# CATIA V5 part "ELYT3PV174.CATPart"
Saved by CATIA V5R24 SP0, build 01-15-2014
Part number: ELYT3PV174
Material "ZAMA": density 6700 kg/m3
Material "ZAMA": density 6700 kg/m3
Bounding box of the stored display mesh (mm): x -59 to 27.5, y 0 to 1740, z 0 to 1500
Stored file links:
  \\mnsrv021stg\Common\AREA TECNICA\Documenti\3D sito\Componenti risolti\ELYT3PV174.CATPart
  Z:\commesse\Novellini\Serie Zephiros\BH01S66\ID_18668_00.CATPart
  Z:\commesse\Novellini\Prove\Tabelladiprogetto1.txt
  Z:\commesse\Novellini\Prove\Tabelladiprogetto2.xls
  C:\Users\n.rebecchi\Desktop\Scambio\ID_35222_00.xls
  Z:\3D sito\BH02A.xlsx
  \\MNSRV021STG\Common\AREA TECNICA\Documenti\3D sito\BOX\ZEPHIROS\BH02A\BH02A.xls
  Z:\3D sito\ZEPHIROS\BH022P\BH022P.xls
  C:\Docisland\DocIsland\catia_workdir\diclient\N.REBECCHI\ID_21111_03.CATPart
  C:\Docisland\DocIsland\catia_workdir\diclient\N.REBECCHI\ID_29051_00.CATPart
  U:\AREA TECNICA\Documenti\3D sito\BOX\ZEPHYROS\ZEPHYR3P\BH013P.xls
  \\mnsrv021stg\Common\AREA TECNICA\Documenti\3D sito\BOX\ELYT\ZEPHYR3P\ELYT3PV.xls
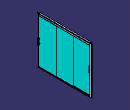
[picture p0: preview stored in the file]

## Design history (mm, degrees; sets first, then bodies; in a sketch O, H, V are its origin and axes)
Parameters
  `Larghezza anta` = 561 mm
  `MISURA NOMINALE` = 1740 mm
  PartNumber = "ELYT3PV174"
  `Lunghezza binario` = 1646 mm
Pad1: profile Sketch3.L13, length 1441, opposite side length -21
Solid1: solid without history
Solid2: solid without history
Pad2: profile Sketch3.L6, length 1441, opposite side length -21
Sketch1 on xy-plane, origin (0, 0, 0), H (1, 0, 0), V (0, 1, 0)
  axis line L1 (84.1025, 870) -> (-125.0839, 870)
  point P3 (-18.5, 0)
  point P4 (-18.5, 52.3)
  point P5 (0, 50.8)
  point P6 (-1.5, 52.3)
  point P8 (0, 1.5)
  point P9 (-1.5, 0)
  line L2 (0, 50.8) -> (0, 1.5)
  line L3 (-1.5, 0) -> (-32.75, 0)
  line L4 (-18.5, 1.5) -> (-18.5, 52.3)
  line L5 (-18.5, 52.3) -> (-1.5, 52.3)
  arc A1 centre (-1.5, 50.8) radius 1.5 from (0, 50.8) to (-1.5, 52.3) ccw
  arc A2 centre (-1.5, 1.5) radius 1.5 from (0, 1.5) to (-1.5, 0) cw
  line L6 (-18.5, 1.5) -> (-32.75, 1.5)
  point P11 (-32.75, 1.5)
  arc A3 centre (-32.75, 0.75) radius 0.75 from (-32.75, 1.5) to (-32.75, 0) ccw
  point P13 (-32.75, 0)
  point P14 (-18.5, 1.5)
  point P15 (-3, 1307.7)
  construction line L7 through (-1555.4, 0) direction (-1, 0)
  construction line L8 through (-1255.4, 0) direction (0, 1)
  point P16 (-18.5, 1740)
  point P17 (-18.5, 1687.7)
  point P18 (0, 1689.2)
  point P19 (-1.5, 1687.7)
  point P21 (0, 1738.5)
  point P22 (-1.5, 1740)
  point P24 (-32.75, 1738.5)
  point P26 (-32.75, 1740)
  point P27 (-18.5, 1738.5)
  line L9 (0, 1689.2) -> (0, 1738.5)
  line L10 (-1.5, 1740) -> (-32.75, 1740)
  line L11 (-18.5, 1738.5) -> (-18.5, 1689.1)
  line L12 (-52, 1687.7) -> (-1.5, 1687.7)
  arc A4 centre (-1.5, 1689.2) radius 1.5 from (0, 1689.2) to (-1.5, 1687.7) cw
  arc A5 centre (-1.5, 1738.5) radius 1.5 from (0, 1738.5) to (-1.5, 1740) ccw
  line L13 (-18.5, 1738.5) -> (-32.75, 1738.5)
  arc A6 centre (-32.75, 1739.25) radius 0.75 from (-32.75, 1738.5) to (-32.75, 1740) cw
  line L14 (-52, 1687.7) -> (-52, 1698.2)
  line L15 (-52, 1698.2) -> (-37, 1698.2)
  line L16 (-37, 1698.2) -> (-37, 1689.1)
  line L17 (-37, 1689.1) -> (-18.5, 1689.1)
  length L5 = 17
  radius A1 = 1.5
  distance L6 L3 = 1.5
  distance L4 A3 = 15
  distance L5 L3 = 52.3
  distance L2 L4 = 18.5
  radius A2 = 1.5
  distance L10 L3 = 1740 {= `MISURA NOMINALE`}
  distance L9 L14 = 52
  length L15 = 15
  distance L12 L17 = 1.4
  distance L15 L12 = 10.5
  tangency: A1 L2, A3 L3, A3 L6, L2 A2, A2 L3
  coincidence: P3 L3, P17 L11, P17 L12, L2 V, L3 L7, L3 H
  symmetry: P3 P16 L1, P4 P17 L1, P5 P18 L1, P6 P19 L1, P8 P21 L1, P9 P22 L1, P11 P24 L1, P13 P26 L1, P14 P27 L1, L2 L9 L1, L3 L10 L1, L4 L11 L1, L5 L12 L1, A1 A4 L1, A2 A5 L1, L6 L13 L1, A3 A6 L1
  vertical: L16 V
Pad3: profile Sketch1, direction (0, 0, 1), length 1500
Body1 "Telaio" (main body)
  Sketch2 on face of Pad3 from Sketch1.L5, origin (0, 52.3, 0), H (-1, 0, 0), V (0, 0, -1)
    point P1 (-1, -1500)
    line L1 (5.7859, -1500) -> (52.2221, -1500)
    line L2 (59, -1485.3692) -> (59, -1437.2118)
    construction line L3 (247.7599, -1440) -> (58, -1440)
    line L4 (-1, -1436.5) -> (-1, -1485.3692)
    point P2 (59, -1500)
    point P3 (59, -1440)
    construction line L5 (57.5, -1498) -> (57.5, -1486.5)
    construction line L6 (190.2599, -1498) -> (4.1139, -1498)
    point P5 (57.5, -1498)
    line L7 (57.7882, -1436) -> (-0.5, -1436)
    construction line L8 (8.597, -1485.5) -> (18.6226, -1485.5)
    construction line L9 (1.7786, -1486.5) -> (4.2562, -1486.5)
    construction line L10 (57.5, -1485.2) -> (57.5, -1440.5)
    construction line L11 (1, -1485) -> (1, -1464.277)
    point P6 (57.5, -1486.5)
    point P7 (1, -1485.5)
    construction line L12 (36.5779, -1495.9874) -> (36.5305, -1488.4874)
    construction line L13 (37.7781, -1496.0126) -> (37.7307, -1488.5126)
    construction line L14 (39.7307, -1486.5) -> (53.9552, -1486.5)
    construction line L15 (39.778, -1498) -> (50.7716, -1498)
    construction line L16 (18.9226, -1496) -> (18.9226, -1488.5)
    construction line L17 (20.1226, -1496) -> (20.1226, -1486.8)
    construction line L18 (20.4226, -1486.5) -> (34.5306, -1486.5)
    construction line L19 (22.1226, -1498) -> (34.5779, -1498)
    construction line L20 (18.9226, -1485.2) -> (18.9226, -1464.6071)
    construction line L21 (20.1226, -1485.2) -> (20.1226, -1466.4658)
    construction line L22 (36.5098, -1485.1981) -> (36.3815, -1464.8702)
    construction line L23 (37.7098, -1485.2019) -> (37.5963, -1467.2104)
    construction line L24 (20.4226, -1485.5) -> (222.4284, -1485.5)
    construction line L25 (38.0098, -1485.5) -> (57.2, -1485.5)
    construction line L26 (0.5, -1461.4168) -> (0.5, -1436.5)
    construction line L27 (46.4222, -1915.0185) -> (46.406, -1912.4534)
    construction line L28 (46.4222, -1915.0185) -> (47.9222, -1915.0091)
    construction arc A1 centre (8.7492, -1464.5115) radius 0.25 from (8.9992, -1464.5065) to (8.701, -1464.7568) cw
    construction arc A2 centre (5.7, -1465.25) radius 2.75 from (3.3803, -1463.773) to (8.3995, -1464.7254) cw
    point P12 (5.7, -1465.25)
    construction line L29 (1.4989, -1463.777) -> (3.3803, -1463.773)
    construction arc A3 centre (4.9238, -1464.5873) radius 4.0762 from (1.9856, -1461.762) to (9, -1464.5873) cw
    point P14 (8.9992, -1464.5065)
    construction arc A4 centre (8.7975, -1464.2662) radius 0.5 from (8.701, -1464.7568) to (8.321, -1464.4175) cw
    point P16 (8.321, -1464.4175)
    point P18 (23.1853, -1465.9683)
    point P19 (21.993, -1463.4903)
    point P20 (25.9312, -1465.8199)
    construction arc A5 centre (23.1853, -1465.9683) radius 2.75 from (21.993, -1463.4903) to (25.9123, -1465.6134) cw
    construction arc A6 centre (26.4305, -1465.7929) radius 0.5 from (25.9918, -1465.553) to (25.9312, -1465.8199) cw
    construction arc A7 centre (26.2112, -1465.6729) radius 0.25 from (26.45, -1465.7469) to (25.9918, -1465.553) cw
    construction arc A8 centre (23.4246, -1466.4658) radius 3.302 from (20.1226, -1466.4658) to (21.993, -1463.4903) cw
    point P24 (21.9929, -1463.4903)
    point P27 (40.6705, -1466.6867)
    construction arc A9 centre (43.6396, -1465.9948) radius 0.25 from (43.8765, -1466.0746) to (43.4818, -1466.1887) cw
    point P30 (43.3164, -1465.9372)
    construction arc A10 centre (43.7975, -1465.8009) radius 0.5 from (43.4818, -1466.1887) to (43.3164, -1465.9372) cw
    construction arc A11 centre (40.6705, -1466.6867) radius 2.75 from (39.5358, -1464.1817) to (43.3323, -1465.9959) cw
    construction arc A12 centre (40.8983, -1467.1895) radius 3.302 from (37.5963, -1467.2104) to (39.5358, -1464.1817) cw
    point P35 (211.7599, -1486.5)
    point P36 (12.6022, -1750.9456)
    point P37 (12.601, -1748.9456)
    point P38 (7.2208, -1496)
    point P39 (11.602, -1750.6462)
    point P40 (7.6073, -1494.5506)
    point P41 (7.6108, -1497.4484)
    point P42 (6.7699, -1497.6909)
    point P43 (5.9208, -1495.2516)
    point P44 (7.9723, -1497.2981)
    point P45 (5.9208, -1495.2516)
    point P46 (6.1845, -1494.2101)
    point P47 (7.9723, -1497.2981)
    point P48 (6.1845, -1494.2101)
    point P49 (6.7699, -1497.6909)
    point P50 (7.6073, -1494.5506)
    point P51 (7.6757, -1497.6898)
    point P52 (8.7353, -1495.1232)
    point P53 (5.9226, -1496.7516)
    point P54 (8.7353, -1495.1232)
    point P55 (5.9226, -1496.7516)
    point P56 (7.9692, -1494.7001)
    point P57 (7.9692, -1494.7001)
    point P58 (7.6108, -1497.4484)
    point P59 (7.6757, -1497.6898)
    construction arc A13 centre (7.2208, -1496) radius 1.5 from (7.6073, -1494.5506) to (7.6108, -1497.4484) ccw
    construction arc A14 centre (7.2208, -1496) radius 1.75 from (5.7042, -1495.1268) to (6.7699, -1497.6909) ccw
    construction line L30 (5.7042, -1495.1268) -> (5.9208, -1495.2516)
    construction arc A15 centre (7.2208, -1496) radius 1.5 from (7.9723, -1497.2981) to (5.9208, -1495.2516) ccw
    construction line L31 (6.1845, -1494.2101) -> (7.9723, -1497.2981)
    construction arc A16 centre (5.5354, -1494.5859) radius 0.75 from (6.1845, -1494.2101) to (5.5317, -1495.3359) ccw
    construction line L32 (6.7699, -1497.6909) -> (7.6073, -1494.5506)
    construction arc A17 centre (7.2208, -1496) radius 1.75 from (7.6757, -1497.6898) to (8.7353, -1495.1232) ccw
    construction line L33 (5.9226, -1496.7516) -> (8.7353, -1495.1232)
    construction arc A18 centre (7.2208, -1496) radius 1.5 from (5.9226, -1496.7516) to (7.9692, -1494.7001) ccw
    construction line L34 (7.9692, -1494.7001) -> (8.2527, -1494.2076)
    construction arc A19 centre (8.9027, -1494.5818) radius 0.75 from (9.4761, -1494.0984) to (8.2527, -1494.2076) ccw
    construction arc A20 centre (7.2208, -1496) radius 2.95 from (4.9609, -1494.1038) to (5.5608, -1493.5613) ccw
    construction line L35 (7.6108, -1497.4484) -> (7.6757, -1497.6898)
    point P60 (196.5645, -1917.6542)
    point P61 (11.6031, -1752.3962)
    point P62 (167.077, -1877.6984)
    construction line L36 (7.2208, -1496) -> (7.769, -1950.7895)
    point P63 (7.769, -1950.7895)
    construction line L37 (7.2208, -1496) -> (-0.9278, -1496)
    point P65 (4.9609, -1494.1038)
    point P67 (7.2232, -1498)
    construction line L38 (10.3276, -1498) -> (16.9226, -1498)
    construction arc A21 centre (4.1139, -1497.5) radius 0.5 from (4.5642, -1497.2826) to (4.1139, -1498) cw
    point P68 (4.5642, -1497.2826)
    construction arc A22 centre (7.2208, -1496) radius 2.95 from (9.4761, -1494.0984) to (9.8774, -1497.2826) cw
    construction arc A23 centre (10.3276, -1497.5) radius 0.5 from (9.8774, -1497.2826) to (10.3276, -1498) ccw
    point P74 (195.3181, -1910.0413)
    point P75 (197.3181, -1910.0413)
    point P77 (195.6181, -1911.0413)
    point P78 (193.8681, -1911.0413)
    point P79 (194.0428, -1910.0413)
    construction line L39 (198.7599, -1909.6171) -> (198.7599, -1904.8275)
    point P81 (196.7599, -1907.6171)
    construction line L40 (7.5212, -1762.7716) -> (7.5105, -1745.0224)
    point P85 (2.4259, -1750.9517)
    point P86 (2.4247, -1748.9517)
    point P88 (3.4257, -1750.6511)
    point P89 (3.4268, -1752.4011)
    point P90 (-151.896, -1877.8906)
    point P91 (7.5, -1950.7897)
    construction line L41 (7.5, -1935.9877) -> (7.5, -1950.7897)
    point P92 (7.5, -1497.9998)
    point P93 (2.4259, -1750.9517)
    point P94 (2.4247, -1748.9517)
    point P95 (7.5, -1487)
    point P96 (3.4257, -1750.6511)
    point P97 (7.8882, -1488.4489)
    point P98 (7.1118, -1488.4489)
    point P99 (7.9529, -1488.6904)
    point P100 (8.799, -1486.25)
    point P101 (8.25, -1485.701)
    point P102 (8.799, -1486.25)
    point P103 (8.5378, -1485.2025)
    point P104 (8.25, -1485.701)
    point P105 (8.5378, -1485.2025)
    point P106 (7.9529, -1488.6904)
    point P107 (7.8882, -1488.4489)
    point P108 (7.0471, -1488.6904)
    point P109 (5.9845, -1486.125)
    point P110 (6.201, -1486.25)
    point P111 (5.9845, -1486.125)
    point P112 (6.201, -1486.25)
    point P113 (6.75, -1485.701)
    point P114 (6.75, -1485.701)
    point P115 (7.1118, -1488.4489)
    point P116 (7.0471, -1488.6904)
    point P117 (3.4268, -1752.4011)
    point P118 (-151.896, -1877.8906)
    point P119 (7.5, -1950.7897)
    construction line L42 (7.5, -1487) -> (7.5, -1950.7897)
    point P120 (6.4659, -1485.2089)
    point P121 (7.5, -1497.9998)
    construction arc A24 centre (7.5, -1487) radius 1.5 from (7.8882, -1488.4489) to (7.1118, -1488.4489) cw
    construction arc A25 centre (7.5, -1487) radius 1.75 from (9.0155, -1486.125) to (7.9529, -1488.6904) cw
    construction line L43 (9.0155, -1486.125) -> (8.799, -1486.25)
    construction arc A26 centre (7.5, -1487) radius 1.5 from (8.25, -1485.701) to (8.799, -1486.25) cw
    construction line L44 (8.2506, -1485.7) -> (8.25, -1485.701)
    construction arc A27 centre (9.1873, -1485.5775) radius 0.75 from (8.5378, -1485.2025) to (9.6782, -1485.0105) cw
    construction line L45 (7.9529, -1488.6904) -> (7.8882, -1488.4489)
    construction arc A28 centre (7.5, -1487) radius 1.75 from (7.0471, -1488.6904) to (5.9845, -1486.125) cw
    construction line L46 (6.201, -1486.25) -> (5.9845, -1486.125)
    construction arc A29 centre (7.5, -1487) radius 1.5 from (6.201, -1486.25) to (6.75, -1485.701) cw
    construction line L47 (6.75, -1485.701) -> (6.7494, -1485.7)
    construction arc A30 centre (5.8164, -1485.5839) radius 0.75 from (5.2424, -1485.1011) to (6.4659, -1485.2089) cw
    construction arc A31 centre (7.5, -1487) radius 2.95 from (5.0963, -1485.2898) to (5.2424, -1485.1011) cw
    construction line L48 (7.1118, -1488.4489) -> (7.0471, -1488.6904)
    construction arc A32 centre (7.5, -1487) radius 2.95 from (4.5556, -1486.8185) to (10.45, -1487) ccw
    construction arc A33 centre (4.2562, -1486.8) radius 0.3 from (4.5556, -1486.8185) to (4.2562, -1486.5) ccw
    construction line L49 (16.9226, -1486.5) -> (10.95, -1486.5)
    construction arc A34 centre (10.95, -1487) radius 0.5 from (10.45, -1487) to (10.95, -1486.5) cw
    construction arc A35 centre (10.7882, -1483.9966) radius 1.5034 from (9.6782, -1485.0105) to (10.7882, -1485.5) ccw
    point P129 (9.6782, -1485.0105)
    point P130 (10.7882, -1485.5)
    construction line L50 (1.5, -1485.5) -> (6.403, -1485.5)
    construction arc A36 centre (4.6889, -1485) radius 0.5 from (5.0963, -1485.2898) to (4.6889, -1485.5) cw
    point P134 (4.6889, -1485.5)
    point P136 (9.6782, -1485.0105)
    construction arc A37 centre (6.403, -1485.9) radius 0.4 from (6.403, -1485.5) to (6.7494, -1485.7) cw
    construction arc A38 centre (8.597, -1485.9) radius 0.4 from (8.597, -1485.5) to (8.2506, -1485.7) ccw
    construction line L51 (191.961, -1463.0884) -> (240.5943, -1463.7586)
    construction line L52 (194.4697, -1470.2529) -> (261.0074, -1472.9865)
    construction circle A39 centre (7.2208, -1496) radius 1.75
    construction arc A40 centre (-0.5, -1499.5) radius 0.5 from (-1, -1499.5) to (-0.5, -1500) ccw
    point P147 (-1, -1499.5)
    point P148 (-0.5, -1500)
    construction arc A41 centre (58.5, -1499.5) radius 0.5 from (58.5, -1500) to (59, -1499.5) ccw
    point P150 (58.5, -1500)
    point P151 (59, -1499.5)
    arc A42 centre (-0.5, -1436.5) radius 0.5 from (-1, -1436.5) to (-0.5, -1436) cw
    construction arc A43 centre (0, -1436.5) radius 0.5 from (0, -1436) to (0.5, -1436.5) cw
    point P156 (0, -1436)
    construction arc A44 centre (58, -1440.5) radius 0.5 from (57.5, -1440.5) to (58, -1440) cw
    line L53 (-0.9205, -1485.76) -> (4.8654, -1499.3908)
    point P163 (-1, -1485.5727)
    arc A45 centre (5.7859, -1499) radius 1 from (4.8654, -1499.3908) to (5.7859, -1500) ccw
    point P164 (4.8654, -1499.3908)
    point P165 (5.7859, -1500)
    construction arc A46 centre (5.5292, -1495.8359) radius 0.5 from (5.5317, -1495.3359) to (5.0689, -1496.0313) cw
    construction arc A47 centre (1.7786, -1487) radius 0.5 from (1.3183, -1487.1954) to (1.7786, -1486.5) cw
    construction arc A48 centre (1.5, -1485) radius 0.5 from (1, -1485) to (1.5, -1485.5) ccw
    construction arc A49 centre (18.6226, -1485.2) radius 0.3 from (18.9226, -1485.2) to (18.6226, -1485.5) cw
    construction arc A50 centre (20.4226, -1485.2) radius 0.3 from (20.1226, -1485.2) to (20.4226, -1485.5) ccw
    construction arc A51 centre (16.9226, -1488.5) radius 2 from (16.9226, -1486.5) to (18.9226, -1488.5) cw
    construction line L54 (29, -1900.3555) -> (29, -1979.6079)
    point P187 (53.1346, -1499.3908)
    line L55 (58.9205, -1485.76) -> (53.1346, -1499.3908)
    arc A52 centre (52.2141, -1499) radius 1 from (53.1345, -1499.3908) to (52.2221, -1500) cw
    point P190 (59, -1485.5727)
    construction line L56 (55.7962, -1489.2815) -> (52.6126, -1496.7815)
    point P191 (-104.6902, -1867.3637)
    point P192 (-110.5556, -1881.1818)
    construction line L57 (59, -1485.5727) -> (-104.6902, -1867.3637)
    construction line L58 (53.1346, -1499.3908) -> (-110.5556, -1881.1818)
    construction line L59 (1.0011, -1461.9168) -> (1.6263, -1461.9155)
    construction arc A53 centre (1, -1461.4168) radius 0.5 from (0.5, -1461.4168) to (1.0011, -1461.9168) ccw
    construction arc A54 centre (1.6252, -1461.4155) radius 0.5 from (1.9856, -1461.762) to (1.6263, -1461.9155) cw
    construction arc A55 centre (22.7726, -1464.6071) radius 3.85 from (18.9226, -1464.6071) to (26.6226, -1464.6074) cw
    construction arc A56 centre (40.2297, -1464.8459) radius 3.8483 from (36.3815, -1464.8702) to (44.0779, -1464.8216) cw
    point P202 (40.2827, -1460.998)
    point P204 (43.8765, -1466.0746)
    point P205 (26.45, -1465.7469)
    arc A57 centre (0, -1485.3692) radius 1 from (-1, -1485.3692) to (-0.9205, -1485.76) ccw
    arc A58 centre (58, -1485.3692) radius 1 from (59, -1485.3692) to (58.9205, -1485.76) cw
    construction arc A59 centre (36.2098, -1485.2) radius 0.3 from (36.5098, -1485.1981) to (36.2098, -1485.5) cw
    construction arc A60 centre (38.0098, -1485.2) radius 0.3 from (37.7098, -1485.2019) to (38.0098, -1485.5) ccw
    construction arc A61 centre (39.7307, -1488.5) radius 2 from (37.7307, -1488.5126) to (39.7307, -1486.5) cw
    construction arc A62 centre (34.5306, -1488.5) radius 2 from (34.5306, -1486.5) to (36.5305, -1488.4874) cw
    construction arc A63 centre (34.5779, -1496) radius 2 from (36.5779, -1495.9874) to (34.5779, -1498) cw
    construction arc A64 centre (39.778, -1496) radius 2 from (37.7781, -1496.0126) to (39.778, -1498) ccw
    construction arc A65 centre (22.1226, -1496) radius 2 from (20.1226, -1496) to (22.1226, -1498) ccw
    construction arc A66 centre (16.9226, -1496) radius 2 from (18.9226, -1496) to (16.9226, -1498) cw
    construction arc A67 centre (50.7716, -1496) radius 2 from (52.6126, -1496.7815) to (50.7716, -1498) cw
    construction arc A68 centre (57.2, -1485.2) radius 0.3 from (57.5, -1485.2) to (57.2, -1485.5) cw
    construction arc A69 centre (1.5, -1464.277) radius 0.5 from (1, -1464.277) to (1.4989, -1463.777) cw
    construction arc A70 centre (53.9552, -1488.5) radius 2 from (53.9552, -1486.5) to (55.7962, -1489.2815) cw
    construction line L60 (1.3183, -1487.1954) -> (5.0689, -1496.0313)
    point P247 (162.3117, -1866.472)
    point P248 (168.0976, -1880.1028)
    construction line L61 (-0.9205, -1485.76) -> (162.3117, -1866.472)
    construction line L62 (4.8654, -1499.3908) -> (168.0976, -1880.1028)
    construction line L63 (57.3536, -1460.1464) -> (55.6464, -1461.8536)
    point P251 (57.5, -1460)
    construction line L64 (55.5, -1462.2071) -> (55.5, -1485)
    point P252 (55.5, -1485.5)
    construction arc A71 centre (55, -1485) radius 0.5 from (55.5, -1485) to (55, -1485.5) cw
    point P254 (55, -1485.5)
    construction arc A72 centre (56, -1462.2071) radius 0.5 from (55.5, -1462.2071) to (55.6464, -1461.8536) cw
    construction arc A73 centre (57, -1459.7929) radius 0.5 from (57.5, -1459.7929) to (57.3536, -1460.1464) cw
    point P259 (57.5, -1459.7929)
    construction line L65 (9, -1464.5873) -> (9, -1465.2632)
    construction arc A74 centre (8.7, -1465.2632) radius 0.3 from (9, -1465.2632) to (8.4, -1465.2632) cw
    construction line L66 (8.3995, -1464.7254) -> (8.4, -1465.2632)
    axis line L67 (204.6582, -1469.5884) -> (238.7986, -1470.2896)
    construction line L68 (26.6226, -1464.6074) -> (26.6225, -1465.5674)
    construction arc A75 centre (26.2659, -1465.5674) radius 0.3566 from (25.9123, -1465.6134) to (26.6225, -1465.5674) ccw
    construction line L69 (44.0779, -1464.8216) -> (44.0847, -1465.8974)
    construction arc A76 centre (43.7024, -1465.8999) radius 0.3823 from (43.3323, -1465.9959) to (44.0847, -1465.8974) ccw
    point P279 (213.6284, -1912.5175)
    point P280 (222.8519, -1905.6947)
    point P281 (220.8519, -1903.6947)
    point P282 (222.4284, -1485.5)
    point P283 (222.4284, -1485.5)
    construction line L70 (222.4284, -1485.5) -> (36.2098, -1485.5)
    construction arc A77 centre (20.4226, -1486.8) radius 0.3 from (20.1226, -1486.8) to (20.4226, -1486.5) cw
    arc A78 centre (57.7882, -1437.2118) radius 1.2118 from (57.7882, -1436) to (59, -1437.2118) cw
    point P290 (0, 0)
    point P291 (0, 0)
    point P304 (0.6, -33)
    line L71 (0.5, 0) -> (48.5, 0)
    line L72 (50, -1.5) -> (50, -11.2929)
    line L73 (0, -17.5) -> (48.1743, -13.2853)
    line L74 (-0.5, -35) -> (0.0954, -35)
    line L75 (-1, -34.5) -> (-1, -1.5)
    arc A79 centre (0.5, -1.5) radius 1.5 from (-1, -1.5) to (0.5, 0) cw
    line L76 (0, -32.0835) -> (0, -17.5)
    arc A80 centre (-0.5, -34.5) radius 0.5 from (-1, -34.5) to (-0.5, -35) ccw
    arc A81 centre (48, -11.2929) radius 2 from (48.1743, -13.2853) to (50, -11.2929) ccw
    line L77 (0.6, -34.4954) -> (0.6, -33)
    arc A82 centre (0.0954, -34.4954) radius 0.5046 from (0.0954, -35) to (0.6, -34.4954) ccw
    arc A83 centre (0.1, -33) radius 0.5 from (0.3, -32.5417) to (0.6, -33) cw
    arc A84 centre (0.5, -32.0835) radius 0.5 from (0.3, -32.5417) to (0, -32.0835) cw
    arc A85 centre (48.5, -1.5) radius 1.5 from (50, -1.5) to (48.5, 0) ccw
    reference intersected line E1 through (0, 0) direction (0, -1) from face of Pad3 from Sketch1.L2
    reference intersected line E2 (18.5, -1500) -> (1.5, -1500) from end face of Pad3
    point P312 (0, -17.5)
    distance L2 L5 = 1.5
    distance L1 L6 = 2
    distance L8 L9 = 1
    distance L20 L21 = 1.2
    distance L22 L23 = 1.2
    distance L11 L20 = 17.9226 (reference)
    distance L23 L27 = 6
    radius A1 = 0.25
    radius A2 = 2.75
    distance L11 P12 = 4.7 (reference)
    radius A4 = 0.5
    radius A7 = 0.25
    radius A6 = 0.5
    radius A5 = 2.75
    radius A11 = 2.75
    radius A9 = 0.25
    radius A10 = 0.5
    radius A14 = 1.75
    distance A14 A15 = 0.25
    radius A13 = 1.5
    radius A20 = 2.95
    angle L31 L36 = 330
    angle L34 L31 = 60
    angle L30 L31 = 30
    angle L32 L35 = 30
    angle L35 L33 = 105
    radius A19 = 0.75
    radius A16 = 0.75
    angle L34 L33 = 30
    angle L31 L30 = 30 (reference)
    radius A21 = 0.5
    radius A23 = 0.5
    distance P38 P95 = 9
    radius A33 = 0.3
    radius A34 = 0.5
    radius A35 = 1.5034
    radius A28 = 1.75
    radius A32 = 2.95
    radius A29 = 1.5
    radius A36 = 0.5
    angle L47 L44 = 60
    radius A30 = 0.75
    angle L44 L43 = 30
    radius A27 = 0.75
    angle L42 L48 = 15
    radius A37 = 0.4
    radius A38 = 0.4
    distance P12 L50 = 20.25
    distance L29 P12 = 1.482
    distance A3 L29 = 3.2585
    distance L29 A1 = 1
    distance P18 P27 = 17.5
    radius A12 = 3.302
    radius A8 = 3.302
    radius A3 = 4.0762
    distance A3 P12 V = 3.4134 (reference)
    distance P18 P12 = 17.5
    distance L1 P38 = 4
    radius A40 = 0.5
    distance P2 P3 = 60
    radius A41 = 0.5
    radius A42 = 0.5
    radius A43 = 0.5
    radius A44 = 0.5
    distance L4 P95 = 8.5
    radius A45 = 1
    angle L53 L4 = 157
    distance L4 P165 = 6.7859
    distance P163 L1 = 14.4273 (reference)
    radius A46 = 0.5
    radius A47 = 0.5
    radius A48 = 0.5
    distance L22 P27 = 4.2774
    radius A49 = 0.3
    radius A50 = 0.3
    radius A51 = 2
    distance L4 L26 = 1.5
    length L4 = 48.8692 (reference)
    distance L55 L56 = 1.5
    radius A53 = 0.5
    radius A54 = 0.5
    distance L29 L59 = 1.8612
    distance L11 L4 = 2
    distance L20 A55 = 7.7
    radius A9 = 0.25 (reference)
    distance L22 L69 = 7.6965
    radius A57 = 1
    radius A58 = 1
    radius A59 = 0.3
    radius A60 = 0.3
    radius A61 = 2
    radius A62 = 2
    radius A63 = 2
    radius A64 = 2
    radius A65 = 2
    radius A66 = 2
    radius A67 = 2
    radius A68 = 0.3
    radius A69 = 0.5
    radius A70 = 2
    distance L53 L60 = 1.5
    distance L16 L17 = 1.2 (reference)
    distance L20 L16 = 0
    distance L21 L17 = 0
    distance L22 L12 = 0
    distance L13 L23 = 0
    distance L12 L13 = 1.2 (reference)
    distance L1 L25 = 14.5
    distance P251 L3 = 20
    distance L2 L64 = 3.5
    angle L63 L10 = 135
    radius A71 = 0.5
    radius A72 = 0.5
    radius A73 = 0.5
    radius A74 = 0.3
    distance A74 L51 = 5
    distance L11 L65 = 8 (reference)
    radius A75 = 0.3566 (reference)
    radius A76 = 0.3823 (reference)
    distance L20 L65 = 9.9226
    distance L65 P12 = 3.3
    distance L4 P12 = 6.7
    distance L1 L7 = 64
    radius A77 = 0.3
    radius A78 = 1.2118
    distance L1 H = 1500 (reference)
    distance L71 L74 = 35
    distance L75 E1 = 1
    distance L75 L72 = 51
    distance L75 L76 = 1
    radius A85 = 1.5
    radius A81 = 2
    radius A80 = 0.5
    radius A82 = 0.5046
    distance L75 L77 = 1.6
    radius A83 = 0.5
    radius A84 = 0.5
    radius A79 = 1.5
    distance L2 L4 = 60
    angle L71 L73 = 5
    distance L71 P312 = 17.5
    distance L74 P304 = 2
    coincidence: L5 L10, L9 L14, L6 L15, L9 L18, L6 L19, L8 L24, L24 L25, A8 P24, P24 A5, A8 P19, P19 A5, A14 A17, A13 A15, A18 A13, L34 P38, L31 P38, P47 P44, P43 P45, P59 P51, P49 P42, L32 P38, L35 P38, L33 P38, P53 P55, P54 P52, P57 P56, P48 P46, L30 P38, P41 P58, P40 L32, L6 L38, L36 P67, L6 P67, L38 P67, P102 P100, P104 P101, P105 P103, P106 P99, P107 P97, P111 P109, P112 P110, P114 P113, P115 P98, P116 P108, L9 P35, L8 P7, A28 A25, A26 A24, A29 A26, P129 A31, P136 P129, A31 A32, L44 P95, L43 P95, L48 P95, L50 P134, L47 P120, L8 P130, L44 P103, L8 L50, L4 P1, L1 P1, L1 P2, L2 P2, L3 P3, L2 P3, P147 L4, P148 L1, A20 P68, A16 P65, L11 P7, L50 P7, L49 P35, P150 L1, P151 L2, P192 L56, P5 L15, P191 L56, P6 L14, A56 P202, P202 L51, L4 P163, L53 P163, L2 P190, L55 P190, L60 P62, P247 L60, P248 L60, P251 L10, P252 L25, P251 L63, L64 P252, P14 A3, P16 A2, A5 P20, P205 A55, A11 P30, P204 A56, P259 L10, P254 L25, L24 P282, L24 L70, P283 P282, L7 P156, P50 P40, L71 H, L4 L75, L1 E2
    tangency: A3 A1, A4 A1, A2 A4, A5 A6, A6 A7, A11 A10, A10 A9, A19 L34, A16 L31, A19 A20, A16 A20, A21 L6, A21 A20, A22 A16, A23 A22, A23 L38, A33 A32, A33 L9, L49 A33, A34 A32, A34 L49, A35 A31, A35 L8, L50 A24, A36 A31, A36 L50, L44 A27, L47 A30, A31 A30, A37 L50, A37 L47, A38 L8, A38 L44, L51 A3, L52 A2, L52 A5, A11 L52, A8 A5, A11 A12, A8 L21, A12 L23, A40 L4, A40 L1, A41 L1, A41 L2, A42 L4, A42 L7, A43 L7, A43 L26, A44 L10, A44 L3, A45 L53, A45 L1, A46 A16, A47 L9, A48 L11, A48 L50, A49 L20, A49 L8, A50 L21, A50 L24, A51 L49, A51 L16, A53 L26, A53 L59, A54 L59, A54 A3, A55 L51, L20 A55, A55 A7, A56 L22, A56 L51, A9 A56, A57 L4, A57 L53, A58 L2, A58 L55, A59 L22, A59 L24, A60 L23, A60 L25, A61 L13, A61 L14, A62 L18, A62 L12, A63 L12, A63 L19, A64 L13, A64 L15, A65 L17, A65 L19, A66 L16, A66 L38, A67 L56, A67 L15, A68 L10, A68 L25, A69 L11, A69 L29, A70 L14, A70 L56, A47 L60, A46 L60, A71 L64, A71 L25, A72 L64, A72 L63, A73 L10, A73 L63, L65 A3, L66 A74, L65 A74, L67 A74, A7 L67, L68 A55, A75 L68, A75 A5, A75 L67, L69 A56, A76 L69, A76 A11, L67 A76, A77 L17, A77 L18, A78 L7, A78 L2, L71 A85, L72 A85, L72 A81, A81 L73, A84 L76, L77 A83, L71 A79, L75 A79, A83 A84
    concentricity: A17 A14, A14 P38, P38 A39, A20 A14, A32 A28, A28 P95, A26 A24, A29 A28
    symmetry: P36 P85 L40, P37 P86 L40, P39 P88 L40, P61 P89 L40, P62 P90 L40, P63 P91 L40, L36 L41 L40, P67 P92 L40, P36 P93 L40, P37 P94 L40, P39 P96 L40, P61 P117 L40, P62 P118 L40, P63 P119 L40, L36 L42 L40, P67 P121 L40, L47 L44 L42, L46 L43 L42, L48 L45 L42, L4 L2 L54, P164 P187 L54, L53 L55 L54, A45 A52 L54
  Pad4: profile Sketch2, direction (0, 1, 0), up to face of Pad3 from Sketch1.L12
Body2 "Maniglia sx"
Body3 "Vetro sx"
Body4 "maniglia dx"
Body5 "Vetro centrale"
  Pad5: profile Sketch3.L2, length 1441, opposite side length -21
  Sketch3 on xy-plane, origin (0, 0, 0), H (1, 0, 0), V (0, 1, 0)
    point P1 (-22, 627.7)
    line L1 (-19, 588.9303) -> (-24.9999, 588.9592)
    line L2 (-25, 588.9592) -> (-25, 1149.9592)
    line L3 (-25, 1149.9592) -> (-19, 1149.9379)
    line L4 (-19, 1149.9379) -> (-19, 588.9303)
    point P6 (-39.5, 1407.2062)
    line L5 (-36.5, 1126.7) -> (-42.5, 1126.7213)
    line L6 (-42.5, 1126.7213) -> (-42.5, 1687.7)
    line L7 (-42.5, 1687.7) -> (-36.5, 1687.7)
    line L8 (-36.5, 1687.7) -> (-36.5, 1126.7)
    construction line L9 (-39.5, 1407.2062) -> (-39.5, -213.0288)
    point P12 (-4.5, 331.652)
    line L10 (-1.5, 51.1464) -> (-7.5, 51.1464)
    line L11 (-7.5, 51.1464) -> (-7.5, 612.1752)
    line L12 (-7.5, 612.1752) -> (-1.5, 612.1464)
    line L13 (-1.5, 612.1464) -> (-1.5, 51.1464)
    construction line L14 (-4.5, 331.652) -> (-122.8046, 331.652)
    point P18 (4, -1)
    point P19 (4, 1038.4)
    axis line L15 (-22, 627.7) -> (-154.4866, 627.7)
    reference projected line E1 (-1.5, 1687.7) -> (-48.1743, 1687.7) from edge [face of Pad3 from Sketch1.L12 | face of Pad4 from Sketch2.L73]
    length L2 = 561 {= `Larghezza anta`}
    length L8 = 561 {= `Larghezza anta`}
    length L1 = 6
    length L5 = 6
    length L10 = 6
    length L13 = 561 {= `Larghezza anta`}
    distance L13 L4 = 17.5
    distance L8 L4 = 17.5
    distance L3 L5 = 23.3
    distance L12 L1 = 23.3
    distance L13 V = 1.5
    distance L11 L13 = 6
    distance L4 L2 = 6
    distance L6 L8 = 6
    distance L7 E1 = 0
    equidistance: L2 L4 P1, L5 L7 P6, L6 L8 P6, L10 L12 P12, L11 L13 P12
    vertical: L9 V
Body6 "Vetro dx"
Relations
  Value = `Larghezza anta`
